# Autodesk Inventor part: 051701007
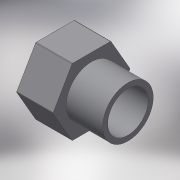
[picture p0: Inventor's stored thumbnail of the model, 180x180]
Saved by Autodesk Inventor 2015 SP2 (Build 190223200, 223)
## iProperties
Created: 2017-10
Part Number: 051701007
Material: Generic
Description: PLASSON THREADED PLUG PVC 3/4"
Document SubType Name: Modeling
Designer: KIM
Density: 1 g/cm^3
Appearance: Default
Author: KIM
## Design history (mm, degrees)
derived "051701.ipt"
feature "Solid1::051701.ipt"
tag "TaggingFeature1"
body "Solid1"
other parameters: "d0" = 32, "d1" = 26.441, "d2" = 1, "d3" = 12, "d6" = 21.1528, "d9" = 12, "d10" = 0, "d18" = 0.3, "d19" = 18, "d20" = 22.4, "R_" = 26.441, "B_" = 12, "Lt_" = 18, "H_" = 32
